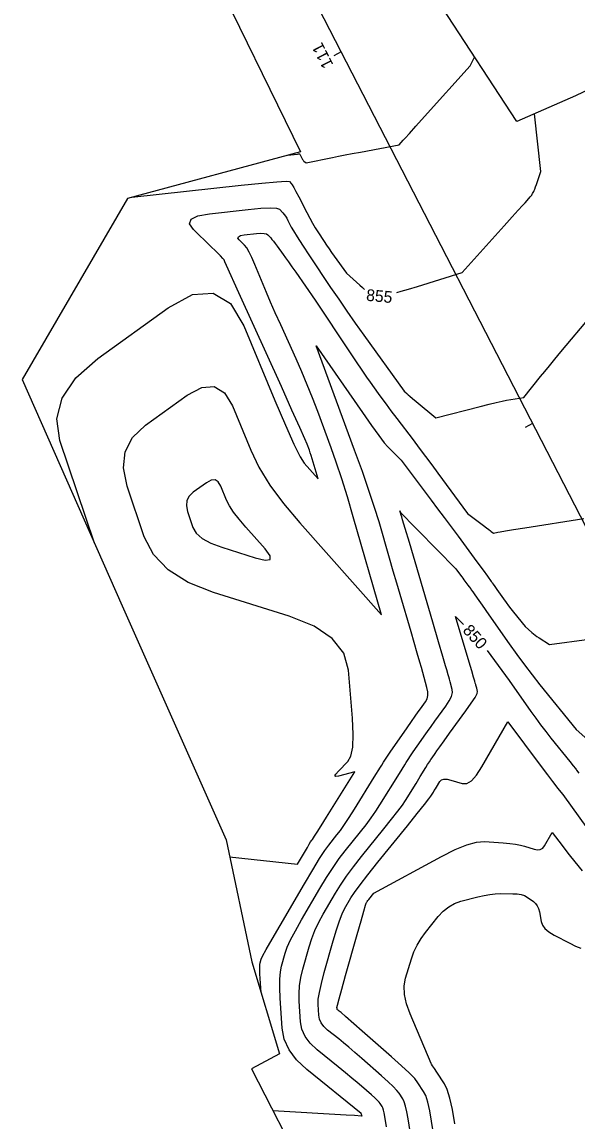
# Model space of a CAD drawing. Extents: x 1715724 to 1716561, y 394063 to 395906.
# Drawn here: x 1715827.7 to 1715894.2, y 395302.7 to 395434.3 of the extents above; entities that cross this region are included whole.
import ezdxf

# ---------------------------------------------------------------- set-up
doc = ezdxf.new("R2010")
doc.units = 0
for name, color, linetype in [('DT_X_Contour_Major', 7, 'Continuous'), ('DT_X_Contour_Minor', 7, 'Continuous'), ('DT_X_TIN_Hull', 7, 'Continuous'), ('GE_P_CL_10', 7, 'Continuous')]:
    doc.layers.add(name, color=color, linetype=linetype)

msp = doc.modelspace()

# ---------------------------------------------------------------- linework, layer by layer
at = {"layer": 'DT_X_Contour_Major'}
for points in [[(1715872.5, 395401.92), (1715873.04, 395402.07), (1715873.91, 395402.32), (1715874.97, 395402.63), (1715880.3, 395404.28), (1715885.33, 395409.87), (1715886.29, 395410.94), (1715887.03, 395411.76), (1715887.54, 395412.33), (1715887.83, 395412.65), (1715888.29, 395413.16), (1715888.44, 395413.33), (1715888.55, 395413.45), (1715888.61, 395413.52), (1715888.63, 395413.54), (1715888.64, 395413.55), (1715888.64, 395413.55), (1715888.64, 395413.55), (1715888.64, 395413.55), (1715888.64, 395413.55), (1715888.65, 395413.56), (1715888.65, 395413.56), (1715888.65, 395413.57), (1715888.67, 395413.61), (1715888.7, 395413.66), (1715888.74, 395413.74), (1715888.87, 395413.98), (1715888.92, 395414.1), (1715889, 395414.28), (1715889.09, 395414.53), (1715889.2, 395414.83), (1715889.74, 395416.38), (1715888.96, 395423.28)], [(1715840.83, 395413.29), (1715853.92, 395414.73), (1715856.39, 395414.99), (1715858.17, 395415.16), (1715859.27, 395415.22), (1715859.69, 395415.18), (1715859.9, 395414.95), (1715860.01, 395414.78), (1715860.2, 395414.46), (1715860.45, 395413.98), (1715860.78, 395413.35), (1715861.74, 395411.46), (1715862.1, 395410.79), (1715862.43, 395410.18), (1715862.75, 395409.64), (1715863.05, 395409.17), (1715863.82, 395408.01), (1715864.11, 395407.58), (1715864.41, 395407.14), (1715864.71, 395406.7), (1715865.03, 395406.26), (1715866.5, 395404.21), (1715868.1, 395402.78), (1715868.42, 395402.49), (1715868.66, 395402.28)], [(1715871.28, 395302.1), (1715871.07, 395303.36), (1715871, 395303.79), (1715870.92, 395304.13), (1715870.84, 395304.39), (1715870.75, 395304.56), (1715870.52, 395304.91), (1715870.4, 395305.08), (1715870.18, 395305.3), (1715869.87, 395305.59), (1715869.47, 395305.95), (1715868.28, 395306.99), (1715867.78, 395307.42), (1715867.15, 395307.95), (1715866.39, 395308.58), (1715865.51, 395309.29), (1715863, 395311.33), (1715862.17, 395312.12), (1715861.56, 395312.94), (1715861.17, 395313.8), (1715861, 395314.69), (1715860.84, 395317.13), (1715860.82, 395318.05), (1715860.89, 395319), (1715861.04, 395319.97), (1715861.28, 395320.96), (1715862.03, 395323.64), (1715862.35, 395324.64), (1715862.73, 395325.62), (1715863.18, 395326.59), (1715863.7, 395327.54), (1715865.17, 395330.06), (1715865.78, 395331.04), (1715866.5, 395332.1), (1715867.33, 395333.23), (1715868.28, 395334.44), (1715870.97, 395337.77), (1715871.88, 395338.91), (1715872.62, 395339.86), (1715873.17, 395340.61), (1715873.54, 395341.15), (1715874.81, 395343.2), (1715875.31, 395344.02), (1715875.96, 395345.08), (1715876.19, 395345.45), (1715876.4, 395345.77), (1715876.57, 395346.04), (1715876.72, 395346.26), (1715877.08, 395346.78), (1715877.28, 395347.07), (1715877.64, 395347.57), (1715878.15, 395348.28), (1715878.81, 395349.19), (1715880.77, 395351.89), (1715881.41, 395352.79), (1715881.86, 395353.48), (1715882.11, 395353.95), (1715882.17, 395354.2), (1715882.06, 395354.58), (1715882.02, 395354.72), (1715881.99, 395354.84), (1715881.96, 395354.93), (1715881.94, 395355.01), (1715881.89, 395355.2), (1715881.82, 395355.41), (1715881.68, 395355.89), (1715881.46, 395356.65), (1715881.15, 395357.69), (1715879.54, 395363.17), (1715880.48, 395362.19)], [(1715883.29, 395359.08), (1715883.74, 395358.49), (1715885.93, 395355.5), (1715888.54, 395351.78), (1715889.11, 395350.98), (1715889.69, 395350.18), (1715890.3, 395349.39), (1715890.93, 395348.6), (1715893.19, 395345.8), (1715893.59, 395345.29), (1715893.85, 395344.98), (1715893.94, 395344.86), (1715894, 395344.79), (1715894.28, 395344.41)]]:
    msp.add_lwpolyline(points, dxfattribs=at)
at = {"layer": 'DT_X_Contour_Minor'}
for points in [[(1715859.45, 395418.33), (1715860.64, 395418.46), (1715860.77, 395418.48), (1715860.85, 395418.48), (1715860.89, 395418.48), (1715860.9, 395418.46), (1715860.94, 395418.39), (1715861.03, 395418.22), (1715861.19, 395417.91), (1715861.25, 395417.81), (1715861.3, 395417.72), (1715861.36, 395417.65), (1715861.41, 395417.61), (1715861.66, 395417.43), (1715864.81, 395418.07), (1715865.52, 395418.21), (1715866.32, 395418.36), (1715867.19, 395418.53), (1715868.15, 395418.71), (1715872.8, 395419.58), (1715873.27, 395420.11), (1715873.51, 395420.37), (1715874.01, 395420.93), (1715874.78, 395421.79), (1715875.82, 395422.94), (1715881.26, 395429), (1715881.81, 395430.05)], [(1715836.39, 395371.91), (1715832.25, 395384.19), (1715831.87, 395386.78), (1715832.5, 395389.28), (1715834.13, 395391.69), (1715836.77, 395394.01), (1715845.17, 395400.08), (1715848.1, 395401.65), (1715850.58, 395401.82), (1715852.63, 395400.58), (1715854.24, 395397.93), (1715857.93, 395389), (1715859.19, 395386.02), (1715860.19, 395383.77), (1715860.94, 395382.27), (1715861.42, 395381.5), (1715863.09, 395379.63), (1715862.51, 395381.62), (1715862.39, 395382.03), (1715862.28, 395382.4), (1715862.17, 395382.73), (1715862.06, 395383.03), (1715861.79, 395383.77), (1715861.52, 395384.4), (1715860.92, 395385.76), (1715859.98, 395387.85), (1715858.71, 395390.65), (1715853.62, 395401.87), (1715852.15, 395405.12), (1715851.94, 395405.59), (1715851.86, 395405.8), (1715851.73, 395405.97), (1715851.42, 395406.3), (1715850.93, 395406.8), (1715850.25, 395407.46), (1715848.21, 395409.45), (1715847.75, 395410.13), (1715847.92, 395410.67), (1715848.71, 395411.07), (1715850.13, 395411.33), (1715854.74, 395411.83), (1715856.27, 395411.98), (1715857.41, 395412.04), (1715858.15, 395412), (1715858.5, 395411.88), (1715858.9, 395411.43), (1715859.05, 395411.25), (1715859.2, 395411.03), (1715859.35, 395410.79), (1715859.5, 395410.51), (1715859.9, 395409.72), (1715860.15, 395409.29), (1715860.6, 395408.57), (1715861.24, 395407.57), (1715862.09, 395406.29), (1715864.6, 395402.51), (1715865.56, 395401.09), (1715866.53, 395399.66), (1715867.53, 395398.23), (1715868.55, 395396.8), (1715873.37, 395390.1), (1715873.61, 395389.89), (1715873.66, 395389.84), (1715873.7, 395389.81), (1715873.73, 395389.78), (1715873.75, 395389.77), (1715873.79, 395389.73), (1715873.87, 395389.66), (1715874.07, 395389.5), (1715874.39, 395389.23), (1715874.83, 395388.86), (1715877.19, 395386.91), (1715882.48, 395388.28), (1715883.53, 395388.55), (1715884.4, 395388.76), (1715885.1, 395388.91), (1715885.62, 395389.01), (1715887.67, 395389.33), (1715889.7, 395391.87), (1715890.18, 395392.46), (1715890.74, 395393.15), (1715891.38, 395393.93), (1715892.11, 395394.81), (1715895.72, 395399.13)], [(1715852.53, 395334.42), (1715860.65, 395333.53), (1715861.82, 395335.52), (1715862.04, 395335.91), (1715862.21, 395336.2), (1715862.34, 395336.4), (1715862.42, 395336.5), (1715862.55, 395336.67), (1715862.69, 395336.88), (1715862.99, 395337.35), (1715863.47, 395338.11), (1715864.11, 395339.14), (1715867.49, 395344.59), (1715865.52, 395344.05), (1715865.2, 395344), (1715865.1, 395344.09), (1715865.21, 395344.31), (1715865.53, 395344.67), (1715866.67, 395345.81), (1715867.03, 395346.46), (1715867.24, 395347.54), (1715867.29, 395349.05), (1715867.2, 395350.99), (1715866.75, 395356.75), (1715866.18, 395358.77), (1715864.8, 395360.52), (1715862.63, 395361.99), (1715859.64, 395363.19), (1715850.62, 395366.01), (1715847.57, 395367.22), (1715845.17, 395368.74), (1715843.42, 395370.56), (1715842.33, 395372.68), (1715840.28, 395378.76), (1715839.84, 395380.92), (1715840.06, 395382.85), (1715840.94, 395384.55), (1715842.48, 395386.02), (1715847.47, 395389.62), (1715849.21, 395390.56), (1715850.69, 395390.65), (1715851.9, 395389.92), (1715852.86, 395388.35), (1715855.05, 395383.04), (1715856.03, 395381), (1715857.34, 395378.88), (1715858.96, 395376.66), (1715860.9, 395374.35), (1715870.69, 395363.37), (1715867.3, 395375.07), (1715866.6, 395377.46), (1715865.92, 395379.64), (1715865.27, 395381.6), (1715864.65, 395383.33), (1715863.05, 395387.67), (1715862.44, 395389.29), (1715861.81, 395390.87), (1715861.15, 395392.43), (1715860.47, 395393.97), (1715858.63, 395398.02), (1715857.98, 395399.46), (1715857.41, 395400.75), (1715856.93, 395401.89), (1715856.52, 395402.87), (1715855.54, 395405.27), (1715855.19, 395406.09), (1715854.87, 395406.75), (1715854.58, 395407.24), (1715854.32, 395407.56), (1715853.66, 395408.19), (1715853.52, 395408.41), (1715853.57, 395408.58), (1715853.82, 395408.71), (1715854.28, 395408.79), (1715855.75, 395408.96), (1715856.25, 395408.99), (1715856.64, 395408.98), (1715856.93, 395408.92), (1715857.11, 395408.8), (1715857.44, 395408.43), (1715857.58, 395408.26), (1715857.76, 395408.04), (1715857.97, 395407.76), (1715858.21, 395407.43), (1715858.91, 395406.47), (1715859.2, 395406.06), (1715859.55, 395405.57), (1715859.96, 395404.99), (1715860.43, 395404.32), (1715862.75, 395400.97), (1715866.84, 395394.83), (1715867.65, 395393.61), (1715868.33, 395392.6), (1715868.89, 395391.78), (1715869.32, 395391.17), (1715870.3, 395389.81), (1715870.71, 395389.24), (1715871.22, 395388.56), (1715871.81, 395387.77), (1715872.5, 395386.85), (1715874.46, 395384.27), (1715875.19, 395383.3), (1715875.93, 395382.3), (1715876.68, 395381.3), (1715877.43, 395380.28), (1715880.96, 395375.48), (1715882.87, 395374.05), (1715883.23, 395373.78), (1715883.51, 395373.57), (1715883.7, 395373.42), (1715883.8, 395373.34), (1715884.07, 395373.12), (1715884.57, 395373.25), (1715884.85, 395373.3), (1715885.49, 395373.41), (1715886.47, 395373.57), (1715887.81, 395373.78), (1715894.86, 395374.88)], [(1715856.29, 395318.18), (1715856.14, 395320.43), (1715856.12, 395320.87), (1715856.12, 395321.24), (1715856.14, 395321.52), (1715856.17, 395321.72), (1715856.3, 395322.16), (1715856.47, 395322.54), (1715856.91, 395323.34), (1715857.6, 395324.56), (1715858.56, 395326.21), (1715861.46, 395331.18), (1715862.46, 395332.86), (1715863.27, 395334.2), (1715863.91, 395335.18), (1715864.37, 395335.82), (1715865.36, 395337.04), (1715865.77, 395337.57), (1715866.25, 395338.26), (1715866.8, 395339.11), (1715867.44, 395340.11), (1715869.82, 395343.94), (1715870.56, 395345.15), (1715870.72, 395345.39), (1715870.93, 395345.74), (1715871.07, 395345.96), (1715871.33, 395346.35), (1715871.72, 395346.91), (1715873.74, 395349.84), (1715874.26, 395350.6), (1715874.7, 395351.23), (1715875.06, 395351.74), (1715875.33, 395352.12), (1715875.95, 395352.96), (1715876.13, 395353.3), (1715876.22, 395353.7), (1715876.21, 395354.16), (1715876.11, 395354.67), (1715875.45, 395357.04), (1715875.26, 395357.69), (1715874.96, 395358.76), (1715874.21, 395361.31), (1715872.9, 395365.77), (1715872.5, 395367.13), (1715872.08, 395368.59), (1715871.62, 395370.15), (1715870.38, 395374.46), (1715869.85, 395376.21), (1715869.18, 395378.22), (1715868.39, 395380.5), (1715867.47, 395383.04), (1715862.86, 395395.54), (1715868.4, 395387.54), (1715869.49, 395385.99), (1715870.35, 395384.8), (1715871.01, 395383.94), (1715871.45, 395383.43), (1715873.01, 395381.84), (1715876.61, 395377.08), (1715877.39, 395376.05), (1715878.18, 395374.98), (1715879, 395373.88), (1715879.83, 395372.75), (1715882.08, 395369.7), (1715882.82, 395368.69), (1715883.35, 395367.97), (1715883.8, 395367.35), (1715883.86, 395367.28), (1715883.91, 395367.2), (1715884.03, 395367.03), (1715884.22, 395366.75), (1715884.48, 395366.38), (1715885.27, 395365.26), (1715885.56, 395364.85), (1715885.86, 395364.45), (1715886.15, 395364.06), (1715886.45, 395363.68), (1715887.85, 395361.94), (1715888.64, 395361.25), (1715888.83, 395361.1), (1715889.03, 395360.94), (1715889.26, 395360.78), (1715889.52, 395360.61), (1715890.77, 395359.81), (1715895.48, 395360.43)], [(1715855.57, 395370.19), (1715856.76, 395369.91), (1715857.36, 395369.98), (1715857.37, 395370.42), (1715856.79, 395371.23), (1715854.45, 395373.85), (1715853.65, 395374.79), (1715853, 395375.64), (1715852.51, 395376.41), (1715852.17, 395377.08), (1715851.47, 395378.76), (1715851.17, 395379.26), (1715850.79, 395379.49), (1715850.32, 395379.46), (1715849.77, 395379.16), (1715848.19, 395378.02), (1715847.7, 395377.56), (1715847.43, 395377.02), (1715847.36, 395376.41), (1715847.49, 395375.73), (1715848.14, 395373.8), (1715848.54, 395373.12), (1715849.25, 395372.49), (1715850.27, 395371.93), (1715851.6, 395371.43), (1715855.57, 395370.19)], [(1715857.69, 395304.09), (1715866.46, 395303.56), (1715867.45, 395303.5), (1715868.27, 395303.45), (1715868.36, 395303.43), (1715868.29, 395303.6), (1715868.28, 395303.63), (1715868.27, 395303.66), (1715868.26, 395303.67), (1715868.26, 395303.68), (1715868.24, 395303.7), (1715861.76, 395308.96), (1715860.54, 395310.12), (1715859.64, 395311.33), (1715859.06, 395312.59), (1715858.81, 395313.9), (1715858.58, 395317.49), (1715858.52, 395318.74), (1715858.53, 395319.79), (1715858.6, 395320.66), (1715858.73, 395321.34), (1715859.16, 395322.9), (1715859.41, 395323.59), (1715859.82, 395324.48), (1715860.39, 395325.58), (1715861.13, 395326.88), (1715863.31, 395330.62), (1715864.12, 395331.95), (1715864.89, 395333.15), (1715865.62, 395334.21), (1715866.33, 395335.13), (1715868.16, 395337.4), (1715868.83, 395338.24), (1715869.43, 395339.06), (1715869.99, 395339.86), (1715870.49, 395340.63), (1715872.81, 395344.38), (1715873.45, 395345.41), (1715873.63, 395345.7), (1715873.87, 395346.06), (1715874.15, 395346.48), (1715874.47, 395346.95), (1715875.41, 395348.31), (1715875.77, 395348.84), (1715876.17, 395349.4), (1715876.61, 395350.01), (1715877.07, 395350.65), (1715878.36, 395352.42), (1715878.77, 395353.05), (1715879.04, 395353.59), (1715879.16, 395354.05), (1715879.14, 395354.43), (1715878.88, 395355.34), (1715878.8, 395355.66), (1715878.72, 395355.94), (1715878.65, 395356.17), (1715878.48, 395356.79), (1715878.34, 395357.27), (1715878.01, 395358.38), (1715877.5, 395360.12), (1715876.8, 395362.48), (1715874.01, 395371.99), (1715873.51, 395373.68), (1715873.2, 395374.71), (1715873.09, 395375.09), (1715873.06, 395375.21), (1715873.04, 395375.25), (1715873.03, 395375.31), (1715873, 395375.37), (1715872.98, 395375.44), (1715872.85, 395375.78), (1715873, 395375.56), (1715873.15, 395375.4), (1715873.54, 395375), (1715874.16, 395374.36), (1715875.01, 395373.48), (1715879.55, 395368.85), (1715880.13, 395368.08), (1715880.26, 395367.91), (1715880.38, 395367.74), (1715880.52, 395367.56), (1715880.65, 395367.38), (1715881.01, 395366.89), (1715881.14, 395366.72), (1715881.34, 395366.45), (1715881.41, 395366.35), (1715881.58, 395366.12), (1715881.75, 395365.88), (1715882.13, 395365.34), (1715882.72, 395364.5), (1715883.52, 395363.35), (1715885.94, 395359.9), (1715886.85, 395358.62), (1715887.76, 395357.38), (1715888.68, 395356.17), (1715889.61, 395355), (1715893.94, 395349.63), (1715896.38, 395347.49)], [(1715874.28, 395300.57), (1715873.87, 395303.07), (1715873.72, 395303.92), (1715873.56, 395304.6), (1715873.4, 395305.12), (1715873.23, 395305.46), (1715872.78, 395306.16), (1715872.52, 395306.48), (1715872.09, 395306.93), (1715871.47, 395307.51), (1715870.68, 395308.22), (1715868.33, 395310.28), (1715867.49, 395311), (1715866.76, 395311.63), (1715866.12, 395312.18), (1715865.57, 395312.63), (1715864.24, 395313.7), (1715863.8, 395314.12), (1715863.48, 395314.55), (1715863.27, 395315.01), (1715863.18, 395315.48), (1715863.1, 395316.77), (1715863.12, 395317.37), (1715863.25, 395318.2), (1715863.49, 395319.27), (1715863.84, 395320.58), (1715864.9, 395324.38), (1715865.29, 395325.69), (1715865.64, 395326.77), (1715865.97, 395327.6), (1715866.27, 395328.21), (1715867.02, 395329.5), (1715867.44, 395330.13), (1715868.11, 395331.05), (1715869.05, 395332.26), (1715870.24, 395333.76), (1715873.77, 395338.13), (1715874.94, 395339.58), (1715875.8, 395340.66), (1715876.35, 395341.35), (1715876.58, 395341.67), (1715876.8, 395342.01), (1715876.89, 395342.16), (1715876.99, 395342.33), (1715877.12, 395342.53), (1715877.26, 395342.76), (1715877.66, 395343.42), (1715877.86, 395343.62), (1715878.14, 395343.71), (1715878.52, 395343.7), (1715878.98, 395343.59), (1715880.33, 395343.17), (1715880.86, 395343.17), (1715881.42, 395343.5), (1715882.03, 395344.16), (1715882.68, 395345.16), (1715885.79, 395350.55), (1715889.76, 395345.22), (1715890.52, 395344.2), (1715891.1, 395343.43), (1715891.5, 395342.9), (1715891.72, 395342.61), (1715892.34, 395341.85), (1715897.13, 395335.22)], [(1715877.27, 395299.04), (1715876.67, 395302.78), (1715876.44, 395304.05), (1715876.2, 395305.08), (1715875.96, 395305.85), (1715875.71, 395306.36), (1715875.04, 395307.4), (1715874.65, 395307.89), (1715874, 395308.56), (1715873.08, 395309.43), (1715871.89, 395310.49), (1715868.37, 395313.56), (1715866.37, 395315.32), (1715865.84, 395315.78), (1715865.63, 395315.96), (1715865.48, 395316.07), (1715865.44, 395316.12), (1715865.4, 395316.17), (1715865.38, 395316.22), (1715865.37, 395316.27), (1715865.36, 395316.4), (1715865.42, 395316.68), (1715865.62, 395317.41), (1715865.94, 395318.58), (1715866.39, 395320.2), (1715867.77, 395325.13), (1715868.23, 395326.75), (1715868.56, 395327.91), (1715868.76, 395328.62), (1715868.84, 395328.87), (1715868.88, 395328.94), (1715868.91, 395328.99), (1715868.97, 395329.06), (1715869.05, 395329.17), (1715869.17, 395329.32), (1715869.77, 395330.07), (1715877.86, 395334.47), (1715879.48, 395335.29), (1715880.88, 395335.86), (1715882.05, 395336.18), (1715883, 395336.24), (1715885.23, 395336.09), (1715886.02, 395336.02), (1715886.7, 395335.93), (1715887.29, 395335.82), (1715887.77, 395335.7), (1715888.91, 395335.33), (1715889.32, 395335.26), (1715889.66, 395335.3), (1715889.94, 395335.46), (1715890.17, 395335.74), (1715891.08, 395337.33), (1715892.25, 395335.76), (1715892.59, 395335.32), (1715893.11, 395334.67), (1715893.8, 395333.8), (1715894.67, 395332.72)], [(1715879.46, 395302.49), (1715879.16, 395304.19), (1715878.84, 395305.55), (1715878.52, 395306.57), (1715878.19, 395307.26), (1715877.29, 395308.65), (1715877, 395309.1), (1715876.79, 395309.43), (1715876.66, 395309.62), (1715876.61, 395309.69), (1715876.6, 395309.7), (1715874.09, 395315.62), (1715873.65, 395316.83), (1715873.42, 395317.95), (1715873.38, 395318.97), (1715873.55, 395319.89), (1715874.25, 395322.2), (1715874.56, 395323.05), (1715874.94, 395323.86), (1715875.4, 395324.63), (1715875.93, 395325.37), (1715877.47, 395327.28), (1715878.06, 395327.93), (1715878.71, 395328.45), (1715879.4, 395328.84), (1715880.15, 395329.1), (1715882.19, 395329.62), (1715882.93, 395329.79), (1715883.62, 395329.91), (1715884.26, 395329.98), (1715884.86, 395330.01), (1715886.37, 395330), (1715886.9, 395329.97), (1715887.36, 395329.9), (1715887.75, 395329.77), (1715888.07, 395329.6), (1715888.83, 395329.08), (1715889.09, 395328.85), (1715889.29, 395328.57), (1715889.45, 395328.22), (1715889.55, 395327.82), (1715889.75, 395326.67), (1715889.9, 395326.24), (1715890.21, 395325.83), (1715890.68, 395325.44), (1715891.31, 395325.06), (1715893.18, 395324.07), (1715893.86, 395323.74), (1715894.49, 395323.48)]]:
    msp.add_lwpolyline(points, dxfattribs=at)
at = {"layer": 'DT_X_TIN_Hull'}
for points in [[(1715850.03, 395441.19), (1715860.99, 395418.75), (1715840.34, 395413.16), (1715827.72, 395391.51), (1715839.7, 395364.44), (1715852.11, 395336.44), (1715855.18, 395321.87), (1715858.5, 395310.84), (1715855.16, 395309.04), (1715867.95, 395284.03), (1715876.16, 395257.29), (1715878.42, 395246.89), (1715878.91, 395238.59), (1715890.8, 395230.97), (1715897.97, 395216.71), (1715912.08, 395192.9)], [(1716036.81, 395207.99), (1716026.44, 395229.43), (1716015.95, 395249.24), (1716007.82, 395269.9), (1716003.67, 395274.88), (1716001.74, 395288.94), (1715989.7, 395309.86), (1715975.1, 395326.33), (1715959.74, 395337.73), (1715947.5, 395351.97), (1715936.7, 395374.51), (1715936.34, 395375.27), (1715926.08, 395398.06), (1715925.19, 395400.05), (1715916.7, 395417.97), (1715910.92, 395433.61), (1715893.86, 395425.44), (1715886.84, 395422.34), (1715877.89, 395436.06)]]:
    msp.add_lwpolyline(points, dxfattribs=at)
at = {"layer": 'GE_P_CL_10'}
for p, q in [((1716249.46, 394685.42), (1715852.54, 395456.56)), ((1715865.86, 395430.68), (1715864.97, 395430.22)), ((1715888.74, 395386.22), (1715887.85, 395385.77))]:
    msp.add_line(p, q, dxfattribs=at)

# ---------------------------------------------------------------- texts
at = {"layer": 'DT_X_Contour_Major'}
for s, rotation, p in [('855', 354.6045, (1715868.8, 395400.93)), ('850', 312.1317, (1715880.3, 395361.43))]:
    msp.add_text(s, height=1.4, rotation=rotation, dxfattribs=at).set_placement(p)
at = {"layer": 'GE_P_CL_10'}
msp.add_text('111', height=1.4, rotation=117.2357, dxfattribs=at).set_placement((1715864.96, 395429.15))

doc.saveas('drawing.dxf')
